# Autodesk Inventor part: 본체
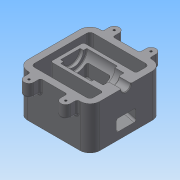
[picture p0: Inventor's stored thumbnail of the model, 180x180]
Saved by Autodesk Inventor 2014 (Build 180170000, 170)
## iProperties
Created: 2018-01
Part Number: 본체
Material: Generic
Document SubType Name: Modeling
Designer: Administrator
Density: 1 g/cm^3
Appearance: Default
Author: Administrator
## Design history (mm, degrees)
sketch "스케치1"
  geometry: L1 (55, -55)-(-55, -55); L2 (-55, -55)-(-55, 55); L3 (-55, 55)-(55, 55); L4 (55, 55)-(55, -55); L5 (55, -55)-(-55, 55); L6 (-55, -55)-(55, 55); L7 (45, -45)-(-45, -45); L8 (-45, -45)-(-45, 45); L9 (-45, 45)-(45, 45); L10 (45, 45)-(45, -45); L11 (45, -45)-(-45, 45); L12 (-45, -45)-(45, 45); 2 further points
  constraints: 24 end point, 6 midpoint, 4 parallel, 2 horizontal, 2 perpendicular, 1 point on line
  dimensions: "d0" = 110 distance of L2.end L3.end; "d1" = 110 distance of L1.end L2.end; "d2" = 90 distance of L8.end L9.end
extrude "돌출1" new body sketch "스케치1" distance "d3" = 65; taper "d4" = 0 deg
fillet "모깎기1" dims "d5" = 15
fillet "모깎기2" dims "d6" = 5
sketch "스케치2"
  geometry: L1 (-55, 40)-(-55, -40) reference; L2 (55, -40)-(55, 40) reference; L3 (40, 55)-(-40, 55) reference; L4 (-55, 40)-(-55, 94.113); L5 (-55, 55)-(55, 55); L6 (-55, 65)-(55, 65); L7 (-28, 40)-(-28, 94.113); L8 (-35.5, 65)-(-35.5, 55); L9 (-20.5, 65)-(-20.5, 55); L10 (-55, 0)-(55, 0); L11 (55, 40)-(55, 103.462); L12 (28, 40)-(28, 103.462); L13 (20.5, 65)-(20.5, 55); L14 (35.5, 65)-(35.5, 55); A1 r 15 centre (-40, 40) between (-40, 55) and (-55, 40) reference; A2 r 15 centre (40, 40) between (55, 40) and (40, 55) reference; A3 r 7.5 centre (-28, 65) between (-35.5, 65) and (-20.5, 65); A4 r 7.5 centre (28, 65) between (20.5, 65) and (35.5, 65); 1 further point
  constraints: 22 end point, 11 point on line, 7 perpendicular, 6 tangent, 4 point on circle, 3 parallel, 2 centre point, 2 midpoint
  dimensions: "d7" = 10 distance between parallel lines of L6 L5; "d8" = 27 distance between parallel lines of L7 L4; "d9" = 15 diameter of A3; "d10" = 27 distance between parallel lines of L11 L12; "d11" = 15 diameter of A4
extrude "돌출2" join sketch "스케치2" distance "d12" = 20; taper "d13" = 0 deg
node "작업 평면1"
sketch "스케치3"
  geometry: L1 (-55, 0)-(-55, 65) reference; L2 (55, 65)-(55, 0) reference; L3 (-40, 65)-(40, 65) reference; L4 (40, 0)-(-40, 0) reference; L5 (-55, 65)-(35, 65); L6 (35, 65)-(35, 30); L7 (35, 30)-(-55, 5.885); L8 (-55, 5.885)-(-55, 65); 1 further point
  constraints: 8 end point, 2 point on line, 1 collinear, 1 perpendicular
  dimensions: "d15" = 90 distance of L1.end L5.end; "d16" = 30 distance from line of L6.end L4; "d17" = 105 deg angle of L6 L7
extrude "돌출3" join sketch "스케치3" stored distance "d18" = 50; taper "d19" = 0 deg
sketch "스케치4"
  geometry: L1 (-55, 0)-(-55, 65) reference; L2 (-55, 65)-(-40, 65) reference; L3 (-55, 65)-(54.184, 65); L4 (-55, 65)-(-55, 57.5); L5 (-36, 57.5)-(-36, 49); L6 (-36, 49)-(-22, 49); L7 (-22, 49)-(-22, 45); L8 (-22, 45)-(25, 45); L9 (25, 45)-(25, 50); L10 (25, 50)-(30, 50); L11 (30, 50)-(30, 65); L12 (-55, 57.5)-(-36, 57.5); 1 further point
  constraints: 20 end point, 5 parallel, 3 perpendicular, 3 point on line
  dimensions: "d21" = 32 diameter of L6 L3; "d22" = 7.5 distance between parallel lines of L2 L12; "d23" = 40 diameter of L8 L3; "d24" = 19 distance of L4.end L5.start; "d25" = 14 distance of L5.end L6.end; "d26" = 47 distance of L7.end L8.end; "d27" = 5 distance of L9.end L10.end; "d28" = 30 diameter of L10 L3
revolve "회전1" sketch "스케치4" stored, may be unused: angle "d29" = 90 deg
sketch "스케치5"
  geometry: L1 (-55, 0)-(-55, 65) reference; L2 (35, 65)-(35, 30) reference; L3 (35, 30)-(-45, 8.564); L4 (-55, 11.061)-(20, 31.157); L5 (-22, 45)-(25, 45) reference; L6 (25, 45)-(25, 65) reference; L7 (30, 50)-(30, 65) reference; L8 (-17, 45)-(-17, 39.243); L9 (-17, 39.243)-(-55, 29.061); L10 (-55, 29.061)-(-55, 11.061); L11 (20, 31.157)-(20, 55); L12 (-17, 45)-(-17, 55); L13 (-17, 60.906)-(20, 60.906); L14 (20, 60.906)-(20, 55); L15 (-17, 60.906)-(-17, 55); L16 (-22, 45)-(-22, 65) reference; 2 further points
  constraints: 20 end point, 5 parallel, 2 perpendicular, 2 point on line, 1 midpoint
  dimensions: "d30" = 5 distance between parallel lines of L3 L4; "d32" = 37 distance of L13.start L13.end; "d42" = 18 distance of L4.start L9.end; "d43" = 5 distance between parallel lines of L12 L16
extrude "돌출4" cut sketch "스케치5" stored distance "d33" = 30; taper "d34" = 0 deg
sketch "스케치6"
  geometry: A1 r 7.5 centre (28, 65) between (35.5, 65) and (20.5, 65) reference; A2 r 7.5 centre (-28, 65) between (-20.5, 65) and (-35.5, 65) reference; A3 r 7.5 centre (-28, -65) between (-35.5, -65) and (-20.5, -65) reference; A4 r 7.5 centre (28, -65) between (20.5, -65) and (35.5, -65) reference; 5 further points
  constraints: 4 coincident
hole "구멍1" sketch "스케치6" at (-28, 65), (28, 65), (28, -65), (-28, -65) diameter "d35" = 3.242; stored, may be unused: countersink angle "d39" = 90 deg, drill point angle "d41" = 118 deg; dims "d36" = 9, "d37" = 4, "d38" = 2, "d40" = 11
sketch "스케치7"
  geometry: L1 (0, 0)-(80, 0) reference; L2 (95.225, 0)-(40.225, 0); L3 (40.225, 0)-(40.225, -20); 2 further points
  constraints: 4 end point, 1 coincident, 1 perpendicular, 1 point on line, 1 other
  dimensions: "d45" = 55 distance of L2.start L2.end; "d46" = 20 distance of L2.end L3.end
feature "엠보싱1" sketch "스케치7" dims "d0" = 110, "d1" = 110, "d2" = 90, "d47" = 0.5, "d48" = 0
fillet "모깎기3" dims "d49" = 3
fillet "모깎기4" dims "d50" = 3
chamfer "모따기1" distance "d51" = 1; stored, may be unused: second distance "d52" = 2, angle "d53" = 45 deg
fillet "모깎기5" dims "d54" = 3
fillet "모깎기6" dims "d55" = 3
fillet "모깎기7" dims "d56" = 3
fillet "모깎기8" dims "d57" = 3
fillet "모깎기9" dims "d58" = 1
chamfer "모따기2" distance "d59" = 1; stored, may be unused: second distance "d60" = 2, angle "d61" = 45 deg
node "솔리드1"
mirror "대칭1"
other parameters: "d14" = 0
